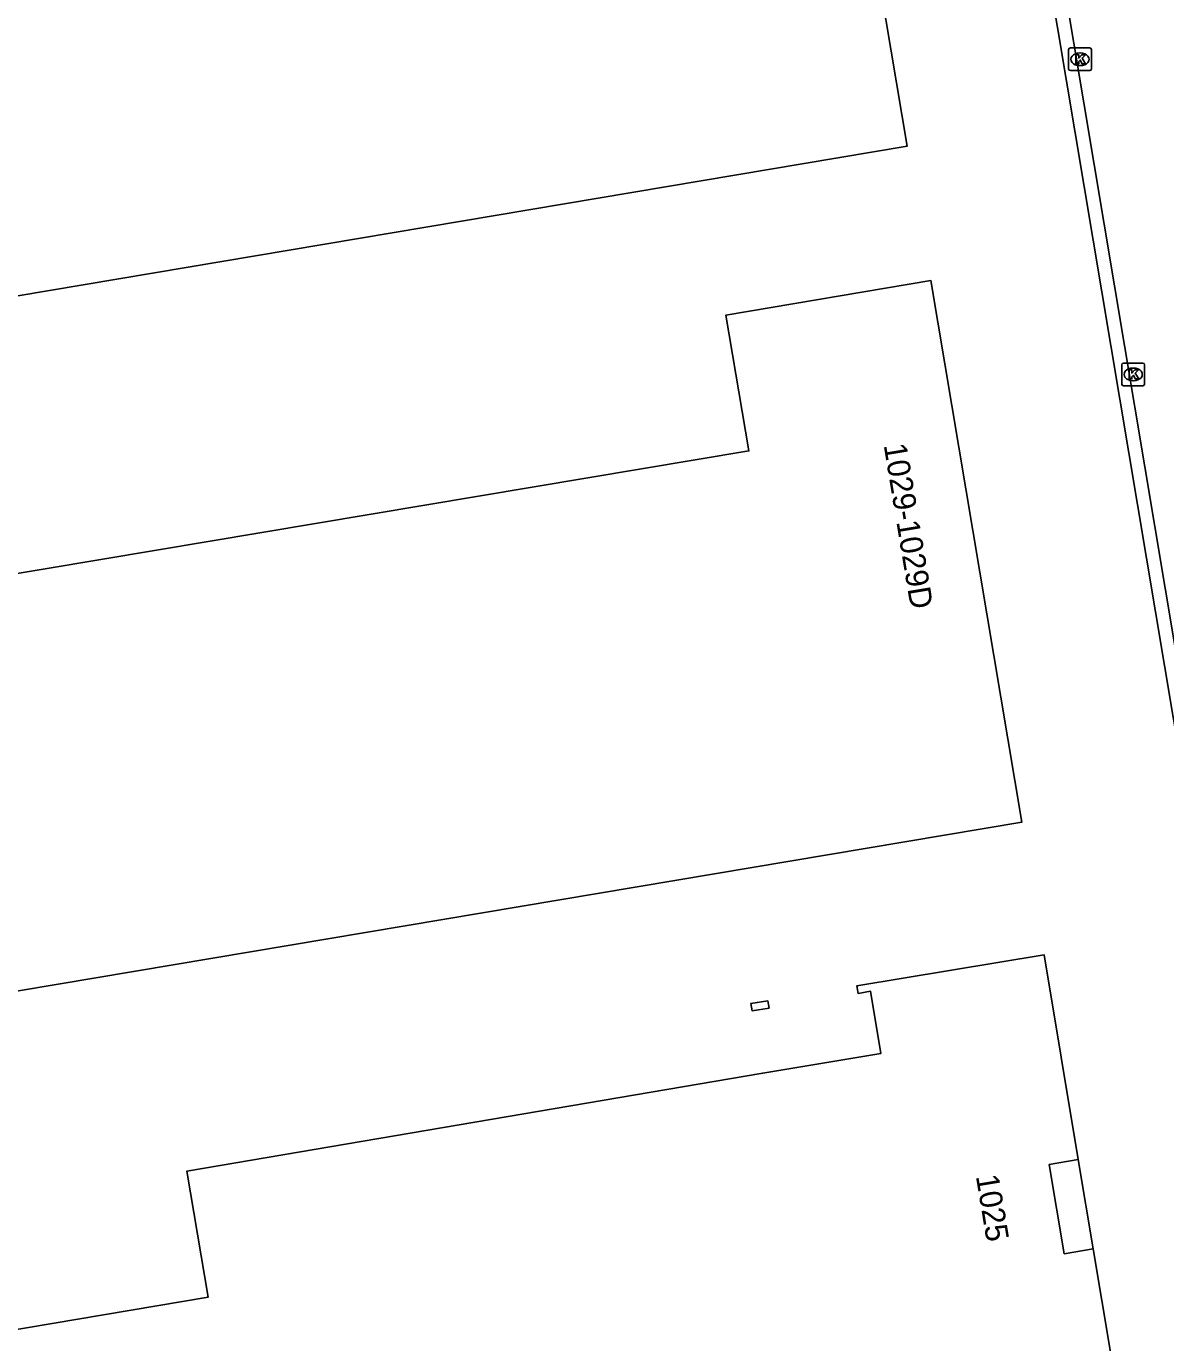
# Model space of a CAD drawing. Extents: x 154324 to 155743, y 382939 to 384183.
# Drawn here: x 155008 to 155058.1, y 383428.3 to 383486.1 of the extents above; entities that cross this region are included whole.
import ezdxf

# ---------------------------------------------------------------- set-up
doc = ezdxf.new("R2010")
doc.units = 0
for name, color, linetype in [('IMGEO_Kolk', 7, 'Continuous'), ('IMGEO_Pand', 7, 'Continuous'), ('IMGEO_Pand_nummerreeks', 7, 'Continuous'), ('IMGEO_Pand_overbouw', 7, 'Continuous'), ('IMGEO_Rijbaan_lokaal_gesloten', 7, 'Continuous'), ('IMGEO_Rijbaan_lokaal_open', 7, 'Continuous')]:
    doc.layers.add(name, color=color, linetype=linetype)

msp = doc.modelspace()

# ---------------------------------------------------------------- linework, layer by layer
at = {"layer": 'IMGEO_Kolk'}
for p, q in [((155053.858, 383484.235), (155053.858, 383485.087)), ((155053.933, 383485.161), (155054.785, 383485.161)), ((155054.859, 383485.087), (155054.859, 383484.235)), ((155054.346, 383484.941), (155054.371, 383484.941)), ((155054.785, 383484.161), (155053.933, 383484.161)), ((155054.369, 383484.381), (155054.344, 383484.381)), ((155056.195, 383470.384), (155056.195, 383471.236)), ((155056.27, 383471.31), (155057.122, 383471.31)), ((155057.196, 383471.236), (155057.196, 383470.384)), ((155056.683, 383471.09), (155056.708, 383471.09)), ((155057.122, 383470.31), (155056.27, 383470.31)), ((155056.706, 383470.53), (155056.681, 383470.53))]:
    msp.add_line(p, q, dxfattribs=at)
for points in [[(155053.858, 383484.235), (155053.858, 383485.087)], [(155053.933, 383485.161), (155054.785, 383485.161)], [(155054.859, 383485.087), (155054.859, 383484.235)], [(155054.179, 383484.861), (155054.302, 383484.861), (155054.302, 383484.71), (155054.432, 383484.861), (155054.596, 383484.861), (155054.45, 383484.71), (155054.603, 383484.461), (155054.451, 383484.461), (155054.366, 383484.625), (155054.302, 383484.558), (155054.302, 383484.461), (155054.179, 383484.461), (155054.179, 383484.861)], [(155054.785, 383484.161), (155053.933, 383484.161)], [(155056.195, 383470.384), (155056.195, 383471.236)], [(155056.27, 383471.31), (155057.122, 383471.31)], [(155057.196, 383471.236), (155057.196, 383470.384)], [(155056.516, 383471.01), (155056.639, 383471.01), (155056.639, 383470.859), (155056.769, 383471.01), (155056.933, 383471.01), (155056.787, 383470.859), (155056.94, 383470.61), (155056.788, 383470.61), (155056.703, 383470.774), (155056.639, 383470.707), (155056.639, 383470.61), (155056.516, 383470.61), (155056.516, 383471.01)], [(155057.122, 383470.31), (155056.27, 383470.31)]]:
    msp.add_lwpolyline(points, dxfattribs=at)
for centre, start, end in [((155053.935, 383485.085), 91.55205, 178.44795), ((155053.935, 383485.085), 91.55205, 178.44795), ((155054.783, 383485.085), 1.55205, 88.44795), ((155054.783, 383485.085), 1.55205, 88.44795), ((155053.935, 383484.237), 181.55205, 268.44795), ((155053.935, 383484.237), 181.55205, 268.44795), ((155054.783, 383484.237), 271.55205, 358.44795), ((155054.783, 383484.237), 271.55205, 358.44795), ((155056.272, 383471.234), 91.55205, 178.44795), ((155056.272, 383471.234), 91.55205, 178.44795), ((155057.12, 383471.234), 1.55205, 88.44795), ((155057.12, 383471.234), 1.55205, 88.44795), ((155056.272, 383470.386), 181.55205, 268.44795), ((155056.272, 383470.386), 181.55205, 268.44795), ((155057.12, 383470.386), 271.55205, 358.44795), ((155057.12, 383470.386), 271.55205, 358.44795)]:
    msp.add_arc(centre, 0.0765, start, end, dxfattribs=at)
for centre, major_axis, ratio, start_param, end_param in [((155054.345, 383484.661), (-0.387, 0.002), 0.722429, 4.712389, 7.853982), ((155054.37, 383484.661), (-0.39, 0.002), 0.717154, 1.570796, 4.712389), ((155056.682, 383470.81), (-0.387, 0.002), 0.722429, 4.712389, 7.853982), ((155056.707, 383470.81), (-0.39, 0.002), 0.717154, 1.570796, 4.712389)]:
    msp.add_ellipse(centre, major_axis=major_axis, ratio=ratio, start_param=start_param, end_param=end_param, dxfattribs=at)
at = {"layer": 'IMGEO_Pand'}
for points in [[(154995.441, 383472.207), (154985.474, 383531.415), (155036.823, 383540.015), (155036.983, 383539.019), (155026.768, 383537.289), (155028.46, 383527.301), (155038.974, 383527.261), (155040.294, 383519.291), (155030.102, 383517.603), (155031.749, 383507.659), (155042.274, 383507.548), (155043.622, 383499.583), (155033.407, 383497.855), (155035.104, 383487.827), (155045.588, 383487.816), (155046.763, 383480.845), (154995.441, 383472.207)], [(154982.713, 383457.883), (155039.8, 383467.448), (155038.784, 383473.411), (155047.804, 383474.933), (155051.795, 383451.133), (154985.613, 383440.023)], [(154987.442, 383425.439), (155016.017, 383430.255), (155015.086, 383435.797), (155040.407, 383440.106), (155045.605, 383440.97), (155045.151, 383443.703), (155044.599, 383443.611), (155044.545, 383443.936), (155052.777, 383445.305), (155054.28, 383436.31), (155053.008, 383436.097), (155053.665, 383432.17), (155054.937, 383432.384), (155056.445, 383423.395), (154989.658, 383412.19)], [(155040.635, 383443.285), (155040.688, 383442.967), (155039.936, 383442.843), (155039.883, 383443.161), (155040.635, 383443.285)]]:
    msp.add_lwpolyline(points, dxfattribs=at)
at = {"layer": 'IMGEO_Pand_overbouw'}
msp.add_lwpolyline([(155054.28, 383436.31), (155053.008, 383436.097), (155053.665, 383432.17), (155054.937, 383432.384)], close=True, dxfattribs=at)
at = {"layer": 'IMGEO_Rijbaan_lokaal_gesloten'}
msp.add_lwpolyline([(155059.439, 383453.463), (155046.503, 383530.572), (155016.871, 383707.197)], dxfattribs=at)
at = {"layer": 'IMGEO_Rijbaan_lokaal_open'}
msp.add_lwpolyline([(155065.709, 383396.485), (155065.341, 383401.33), (155064.659, 383408.986), (155063.139, 383423.564), (155063.03, 383424.403), (155061.613, 383435.27), (155060.487, 383443.041), (155058.846, 383453.397), (155045.918, 383530.449), (155024.164, 383660.104), (155016.277, 383707.107)], dxfattribs=at)

# ---------------------------------------------------------------- texts
at = {"layer": 'IMGEO_Pand_nummerreeks'}
for s, rotation, p in [('1029-1029D', 279.40531, (155045.723, 383467.707)), ('1025', 279.42985, (155049.776, 383435.578))]:
    msp.add_text(s, height=1, rotation=rotation, dxfattribs=at).set_placement(p)

doc.saveas('drawing.dxf')
